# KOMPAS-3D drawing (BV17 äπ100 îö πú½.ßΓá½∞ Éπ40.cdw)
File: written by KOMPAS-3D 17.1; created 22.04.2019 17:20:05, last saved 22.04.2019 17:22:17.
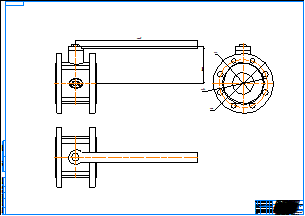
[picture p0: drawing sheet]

Sheet 1: A0, landscape

Title block, sheet 1: name: BV17 Ду100 МФ угл.сталь Ру40; material: Внимание! Данный продукт является объектом авторского права ООО «Торговый Дом АДЛ». / Запрещается изменение, копирование, распространение / (в том числе путем копирования на другие сайты и ресурсы в Интернете) / или любое иное использование информации и объектов без предварительного / согласия правообладателя (ООО «Торговый Дом АДЛ»).; mass: 28,89; sheets: 1; organisation: ООО "Торговый дом АДЛ"; sheet format: A0; stored path: \\adlc.lan\data\АДЛ_ПКД\3D-модели\ADL production\Краны шаровые серии BV\BV17 МФ угл.сталь Ру40\KOMPAS 2D\BV17 Ду100 МФ угл.сталь Ру40.cdw

Views: Вид 1, Проекционный вид 2, Проекционный вид 3
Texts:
  user
Dimensions and other numbers on the sheet: 476,29; 143,5; 85; 190; 235; 1:1; 1; 28,89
